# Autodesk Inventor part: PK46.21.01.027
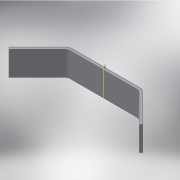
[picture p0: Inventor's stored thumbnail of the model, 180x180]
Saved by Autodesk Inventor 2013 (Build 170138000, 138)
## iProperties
Created: 2005-04
Part Number: PK46.21.01.027
Material: Steel, Mild
Document SubType Name: Sheet Metal
Designer: salex
Manufacturer: Standard
Standards Organization: Custom
Density: 7.86 g/cm^3
Sheet Metal Rule: Default
Author: salex
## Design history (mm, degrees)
node "ФлнОтгиб1"
node "РабПлоскость1"
body "Solid1"
sketch "Эскиз1"
  geometry: L1 (0, 0)-(120, 120); L2 (120, 120)-(410, 120); L3 (410, 120)-(530, 0)
  constraints: 6 end point, 1 horizontal, 1 perpendicular, 1 other
  dimensions: "d0" = 530 distance of L3.end L1.start; "d1" = 120 distance from line of L1.start L2; "d2" = 0 vertical distance of L3.end L1.start; "d3" = 290 distance of L1.end L2.end
feature "Плакирование1" dims "d4" = 100, "d5" = 10 (= BendReliefWidth), "d7" = 20 (= MinimumRemnant), "d9" = 20 (= BendRadius), "d10" = 10, "Thickness" = 10
feature "Изгиб1" dims "d5" = 10 (= BendReliefWidth), "d6" = 5 (= BendReliefDepth), "d7" = 20 (= MinimumRemnant), "d8" = 20 (= BendRadius), "d9" = 20 (= BendRadius), "d10" = 10, "SeamGap" = 0.01, "Thickness" = 10
other parameters: "BendRadius" = 20, "BendReliefDepth" = 5 (= 0.5 x Thickness)
